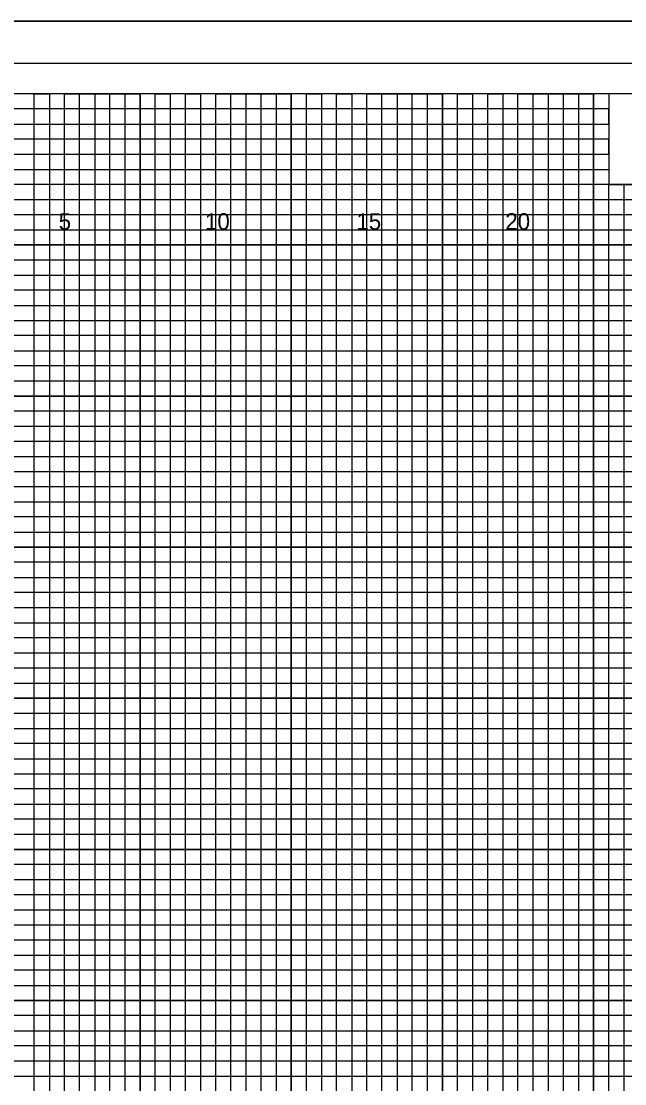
# Model space of a CAD drawing. Extents: x -4 to 103, y -2 to 492.
# Drawn here: x 54.82 to 74.78, y 103.07 to 138.23 of the extents above; entities that cross this region are included whole.
import ezdxf

# ---------------------------------------------------------------- set-up
doc = ezdxf.new("R2010")
doc.units = 0
for name, color, linetype in [('Old_Level_10', 7, 'Continuous'), ('Old_Level_16', 7, 'Continuous'), ('Old_Level_3', 7, 'Continuous'), ('Old_Level_5', 7, 'Continuous'), ('Old_Level_8', 7, 'Continuous'), ('Prop Dimension', 7, 'Continuous'), ('Prop XS SE Text', 7, 'Continuous'), ('Prop XSC Text', 7, 'Continuous')]:
    doc.layers.add(name, color=color, linetype=linetype)

msp = doc.modelspace()

# ---------------------------------------------------------------- linework, layer by layer
at = {"layer": 'Old_Level_10'}
for p, q in [((56.25, 70.825), (56.25, 135.825)), ((58.75, 70.825), (58.75, 135.825)), ((61.25, 70.825), (61.25, 135.825)), ((63.75, 70.825), (63.75, 135.825)), ((66.25, 70.825), (66.25, 135.825)), ((68.75, 70.825), (68.75, 135.825)), ((71.25, 70.825), (71.25, 135.825)), ((73.75, 70.825), (73.75, 135.825)), ((0, 133.325), (74.25, 133.325)), ((0, 130.825), (102.5, 130.825)), ((0, 128.325), (102.5, 128.325)), ((0, 125.825), (102.5, 125.825)), ((0, 123.325), (102.5, 123.325)), ((0, 120.825), (102.5, 120.825)), ((0, 118.325), (102.5, 118.325)), ((0, 115.825), (102.5, 115.825)), ((0, 113.325), (102.5, 113.325)), ((0, 110.825), (102.5, 110.825)), ((0, 108.325), (102.5, 108.325)), ((0, 105.825), (102.5, 105.825)), ((0, 103.325), (102.5, 103.325))]:
    msp.add_line(p, q, dxfattribs=at)
at = {"layer": 'Old_Level_3'}
msp.add_line((-3.5, 138.225), (103.4, 138.225), dxfattribs=at)
at = {"layer": 'Old_Level_5'}
msp.add_lwpolyline([(103.4, 138.225), (-3.5, 138.225), (-3.5, 68.4), (103.4, 68.4)], close=True, dxfattribs=at)
at = {"layer": 'Old_Level_8'}
for points in [[(56.25, 70.825), (56.25, 135.825), (58.75, 135.825), (58.75, 70.825)], [(61.25, 70.825), (61.25, 135.825), (63.75, 135.825), (63.75, 70.825)], [(66.25, 70.825), (66.25, 135.825), (68.75, 135.825), (68.75, 70.825)], [(71.25, 70.825), (71.25, 135.825), (73.75, 135.825), (73.75, 70.825)], [(0, 133.325), (74.25, 133.325)], [(0, 128.325), (102.5, 128.325), (102.5, 130.825), (0, 130.825)], [(0, 123.325), (102.5, 123.325), (102.5, 125.825), (0, 125.825)], [(0, 118.325), (102.5, 118.325), (102.5, 120.825), (0, 120.825)], [(0, 113.325), (102.5, 113.325), (102.5, 115.825), (0, 115.825)], [(0, 108.325), (102.5, 108.325), (102.5, 110.825), (0, 110.825)], [(0, 103.325), (102.5, 103.325), (102.5, 105.825), (0, 105.825)]]:
    msp.add_lwpolyline(points, dxfattribs=at)
at = {"layer": 'Prop Dimension'}
for points in [[(55.25, 70.825), (55.25, 135.825), (55.75, 135.825), (55.75, 70.825)], [(56.75, 70.825), (56.75, 135.825), (57.25, 135.825), (57.25, 70.825)], [(57.75, 70.825), (57.75, 135.825), (58.25, 135.825), (58.25, 70.825)], [(59.25, 70.825), (59.25, 135.825), (59.75, 135.825), (59.75, 70.825)], [(60.25, 70.825), (60.25, 135.825), (60.75, 135.825), (60.75, 70.825)], [(61.75, 70.825), (61.75, 135.825), (62.25, 135.825), (62.25, 70.825)], [(62.75, 70.825), (62.75, 135.825), (63.25, 135.825), (63.25, 70.825)], [(64.25, 70.825), (64.25, 135.825), (64.75, 135.825), (64.75, 70.825)], [(65.25, 70.825), (65.25, 135.825), (65.75, 135.825), (65.75, 70.825)], [(66.75, 70.825), (66.75, 135.825), (67.25, 135.825), (67.25, 70.825)], [(67.75, 70.825), (67.75, 135.825), (68.25, 135.825), (68.25, 70.825)], [(69.25, 70.825), (69.25, 135.825)], [(69.25, 135.825), (69.75, 135.825), (69.75, 70.825)], [(70.25, 70.825), (70.25, 135.825), (70.75, 135.825), (70.75, 70.825)], [(71.75, 70.825), (71.75, 135.825), (72.25, 135.825), (72.25, 70.825)], [(72.75, 70.825), (72.75, 135.825), (73.25, 135.825), (73.25, 70.825)], [(0, 132.825), (0, 133.825), (74.25, 133.825), (74.25, 134.325), (0, 134.325), (0, 134.825), (74.25, 134.825), (74.25, 135.325), (0, 135.325)], [(0, 132.325), (102.5, 132.325), (102.5, 132.825), (0, 132.825)], [(74.25, 70.825), (74.25, 132.825), (74.75, 132.825), (74.75, 70.825)], [(0, 131.325), (102.5, 131.325), (102.5, 131.825), (0, 131.825)], [(0, 129.825), (102.5, 129.825), (102.5, 130.325), (0, 130.325)], [(0, 128.825), (102.5, 128.825), (102.5, 129.325), (0, 129.325)], [(0, 127.325), (102.5, 127.325), (102.5, 127.825), (0, 127.825)], [(0, 126.325), (102.5, 126.325), (102.5, 126.825), (0, 126.825)], [(0, 124.825), (102.5, 124.825), (102.5, 125.325), (0, 125.325)], [(0, 123.825), (102.5, 123.825), (102.5, 124.325), (0, 124.325)], [(0, 122.325), (102.5, 122.325), (102.5, 122.825), (0, 122.825)], [(0, 121.325), (102.5, 121.325), (102.5, 121.825), (0, 121.825)], [(0, 119.825), (102.5, 119.825), (102.5, 120.325), (0, 120.325)], [(0, 118.825), (102.5, 118.825), (102.5, 119.325), (0, 119.325)], [(0, 117.325), (102.5, 117.325), (102.5, 117.825), (0, 117.825)], [(0, 116.325), (102.5, 116.325), (102.5, 116.825), (0, 116.825)], [(0, 114.825), (102.5, 114.825), (102.5, 115.325), (0, 115.325)], [(0, 113.825), (102.5, 113.825), (102.5, 114.325), (0, 114.325)], [(0, 112.325), (102.5, 112.325), (102.5, 112.825), (0, 112.825)], [(0, 111.325), (102.5, 111.325), (102.5, 111.825), (0, 111.825)], [(0, 109.825), (102.5, 109.825), (102.5, 110.325), (0, 110.325)], [(0, 108.825), (102.5, 108.825), (102.5, 109.325), (0, 109.325)], [(0, 107.325), (102.5, 107.325), (102.5, 107.825), (0, 107.825)], [(0, 106.325), (102.5, 106.325), (102.5, 106.825), (0, 106.825)], [(0, 104.825), (102.5, 104.825), (102.5, 105.325), (0, 105.325)], [(0, 103.825), (102.5, 103.825), (102.5, 104.325), (0, 104.325)]]:
    msp.add_lwpolyline(points, dxfattribs=at)
at = {"layer": 'Prop XS SE Text'}
msp.add_lwpolyline([(103, 136.825), (-2.8, 136.825), (-2.8, 69.825), (103, 69.825)], close=True, dxfattribs=at)
at = {"layer": 'Prop XSC Text'}
for points in [[(102.5, 135.825), (0, 135.825), (0, 70.825), (102.5, 70.825)], [(83.75, 135.825), (74.25, 135.825), (74.25, 132.825), (83.75, 132.825)]]:
    msp.add_lwpolyline(points, close=True, dxfattribs=at)

# ---------------------------------------------------------------- texts
at = {"layer": 'Old_Level_16'}
for s, p in [('5', (56.0574, 131.325)), ('10', (60.8971, 131.325)), ('15', (65.9057, 131.325)), ('20', (70.8312, 131.325))]:
    msp.add_text(s, height=0.55, dxfattribs=at).set_placement(p)

doc.saveas('drawing.dxf')
